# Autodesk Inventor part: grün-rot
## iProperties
Created: 2004-10
Part Number: grün-rot
Document SubType Name: Modeling
Designer: sahrens
Manufacturer: Standard
Standards Organization: Custom
Author: sahrens
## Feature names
1. Extrusion1
2. Rundung2 [Fillet]
